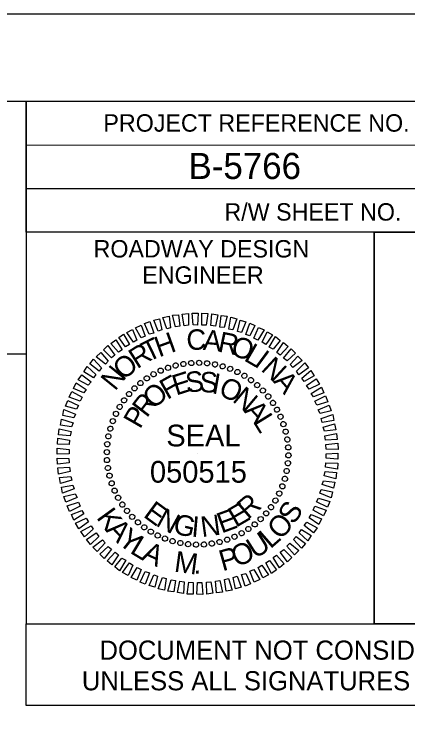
# Model space of a CAD drawing. Extents: x 573078 to 573156.2, y -55225.7 to -55195.8.
# Drawn here: x 573107.444 to 573109.707, y -55203.398 to -55199.298 of the extents above; entities that cross this region are included whole.
import ezdxf

# ---------------------------------------------------------------- set-up
doc = ezdxf.new("R2010")
doc.units = 0
for name, color, linetype in [('Prop Dimension', 7, 'Continuous'), ('Scratch_Level_1', 7, 'Continuous'), ('Sheet Data Field CELL', 7, 'Continuous'), ('Sheet Plan CELL', 7, 'Continuous'), ('Sheet Plot Border Inside CELL', 7, 'Continuous'), ('Sheet Sticker Exception Certification CELL', 7, 'Continuous')]:
    doc.layers.add(name, color=color, linetype=linetype)

msp = doc.modelspace()

# ---------------------------------------------------------------- linework, layer by layer
at = {"layer": 'Prop Dimension'}
for p, q in [((573108.3718, -55201.316), (573108.3718, -55201.316)), ((573108.4176, -55201.3077), (573108.4176, -55201.3077)), ((573108.4623, -55201.3015), (573108.4623, -55201.3015)), ((573108.5081, -55201.3005), (573108.5081, -55201.3005)), ((573108.5539, -55201.3035), (573108.5539, -55201.3035)), ((573108.5988, -55201.3109), (573108.5988, -55201.3109)), ((573108.6425, -55201.3202), (573108.6425, -55201.3202)), ((573108.2864, -55201.3452), (573108.2864, -55201.3452)), ((573108.328, -55201.3285), (573108.328, -55201.3285)), ((573108.6863, -55201.3348), (573108.6863, -55201.3348)), ((573108.7279, -55201.3535), (573108.7279, -55201.3535)), ((573108.2061, -55201.3901), (573108.2061, -55201.3901)), ((573108.2457, -55201.366), (573108.2457, -55201.366)), ((573108.7684, -55201.3744), (573108.7684, -55201.3744)), ((573108.8059, -55201.4005), (573108.8059, -55201.4005)), ((573108.1698, -55201.416), (573108.1698, -55201.416)), ((573108.8425, -55201.4285), (573108.8425, -55201.4285)), ((573108.104, -55201.4796), (573108.104, -55201.4796)), ((573108.1353, -55201.4473), (573108.1353, -55201.4473)), ((573108.8746, -55201.4597), (573108.8746, -55201.4597)), ((573108.076, -55201.516), (573108.076, -55201.516)), ((573108.9059, -55201.4942), (573108.9059, -55201.4942)), ((573108.0499, -55201.5535), (573108.0499, -55201.5535)), ((573108.932, -55201.5306), (573108.932, -55201.5306)), ((573108.0291, -55201.5942), (573108.0291, -55201.5942)), ((573108.9559, -55201.5701), (573108.9559, -55201.5701)), ((573108.0103, -55201.6359), (573108.0103, -55201.6359)), ((573108.9767, -55201.6109), (573108.9767, -55201.6109)), ((573107.9957, -55201.6796), (573107.9957, -55201.6796)), ((573108.9934, -55201.6525), (573108.9934, -55201.6525)), ((573107.9865, -55201.7233), (573107.9865, -55201.7233)), ((573109.0059, -55201.6963), (573109.0059, -55201.6963)), ((573107.9791, -55201.768), (573107.9791, -55201.768)), ((573109.0142, -55201.7421), (573109.0142, -55201.7421)), ((573109.0204, -55201.7867), (573109.0204, -55201.7867)), ((573107.9761, -55201.8138), (573107.9761, -55201.8138)), ((573108.4988, -55201.8233), (573108.4988, -55201.8233)), ((573109.0216, -55201.8326), (573109.0216, -55201.8326)), ((573107.977, -55201.8596), (573107.977, -55201.8596)), ((573109.0184, -55201.8784), (573109.0184, -55201.8784)), ((573107.9832, -55201.9045), (573107.9832, -55201.9045)), ((573109.0112, -55201.9233), (573109.0112, -55201.9233)), ((573107.9916, -55201.9504), (573107.9916, -55201.9504)), ((573109.0017, -55201.967), (573109.0017, -55201.967)), ((573108.0041, -55201.9941), (573108.0041, -55201.9941)), ((573108.9871, -55202.0108), (573108.9871, -55202.0108)), ((573108.0207, -55202.0357), (573108.0207, -55202.0357)), ((573108.9684, -55202.0524), (573108.9684, -55202.0524)), ((573108.0415, -55202.0762), (573108.0415, -55202.0762)), ((573108.9475, -55202.0929), (573108.9475, -55202.0929)), ((573108.0656, -55202.1158), (573108.0656, -55202.1158)), ((573108.9216, -55202.1304), (573108.9216, -55202.1304)), ((573108.0915, -55202.1524), (573108.0915, -55202.1524)), ((573108.8934, -55202.167), (573108.8934, -55202.167)), ((573108.1228, -55202.1866), (573108.1228, -55202.1866)), ((573108.1552, -55202.2179), (573108.1552, -55202.2179)), ((573108.8622, -55202.1991), (573108.8622, -55202.1991)), ((573108.1915, -55202.2461), (573108.1915, -55202.2461)), ((573108.7913, -55202.2565), (573108.7913, -55202.2565)), ((573108.8279, -55202.2304), (573108.8279, -55202.2304)), ((573108.229, -55202.272), (573108.229, -55202.272)), ((573108.2697, -55202.2929), (573108.2697, -55202.2929)), ((573108.7113, -55202.3012), (573108.7113, -55202.3012)), ((573108.7518, -55202.2804), (573108.7518, -55202.2804)), ((573108.3114, -55202.3116), (573108.3114, -55202.3116)), ((573108.3551, -55202.3262), (573108.3551, -55202.3262)), ((573108.3989, -55202.3357), (573108.3989, -55202.3357)), ((573108.4435, -55202.3428), (573108.4435, -55202.3428)), ((573108.5352, -55202.3449), (573108.5352, -55202.3449)), ((573108.5801, -55202.3387), (573108.5801, -55202.3387)), ((573108.6259, -55202.3303), (573108.6259, -55202.3303)), ((573108.6696, -55202.3178), (573108.6696, -55202.3178)), ((573108.4893, -55202.3461), (573108.4893, -55202.3461))]:
    msp.add_line(p, q, dxfattribs=at)
for points in [[(573108.3218, -55201.1057), (573108.2998, -55201.0402), (573108.3352, -55201.0328), (573108.3435, -55201.1006)], [(573108.3718, -55201.0943), (573108.3551, -55201.0277), (573108.3894, -55201.0245), (573108.3968, -55201.0911)], [(573108.4218, -55201.0881), (573108.4102, -55201.0214), (573108.4456, -55201.0173), (573108.4468, -55201.0849)], [(573108.4738, -55201.0828), (573108.4685, -55201.0152), (573108.503, -55201.0161), (573108.4988, -55201.0839)], [(573108.5238, -55201.0839), (573108.5238, -55201.0161), (573108.5581, -55201.0173), (573108.5488, -55201.0848)], [(573108.5759, -55201.0869), (573108.5801, -55201.0194), (573108.6143, -55201.0256), (573108.6009, -55201.0911)], [(573108.6259, -55201.0953), (573108.6351, -55201.0286), (573108.6696, -55201.0339), (573108.6509, -55201.0985)], [(573108.2207, -55201.136), (573108.1936, -55201.0756), (573108.2248, -55201.0631), (573108.2468, -55201.1297)], [(573108.2718, -55201.1193), (573108.2477, -55201.0568), (573108.2801, -55201.0474), (573108.2936, -55201.1119)], [(573108.6789, -55201.1068), (573108.6893, -55201.039), (573108.7247, -55201.0474), (573108.7009, -55201.1119)], [(573108.7289, -55201.1203), (573108.7446, -55201.0557), (573108.7768, -55201.0661), (573108.7508, -55201.1277)], [(573108.7758, -55201.139), (573108.7997, -55201.0735), (573108.8288, -55201.086), (573108.7997, -55201.1464)], [(573108.1302, -55201.1827), (573108.0915, -55201.1265), (573108.1239, -55201.1098), (573108.1499, -55201.1702)], [(573108.1748, -55201.1577), (573108.1415, -55201.0994), (573108.1739, -55201.0849), (573108.1978, -55201.1485)], [(573108.8226, -55201.1589), (573108.8487, -55201.0974), (573108.8809, -55201.1119), (573108.8455, -55201.1702)], [(573108.0844, -55201.2089), (573108.0457, -55201.1557), (573108.0728, -55201.136), (573108.1073, -55201.1964)], [(573108.8705, -55201.1827), (573108.8987, -55201.1235), (573108.93, -55201.1411), (573108.8904, -55201.1952)], [(573108.9112, -55201.211), (573108.9475, -55201.1506), (573108.9746, -55201.1723), (573108.9341, -55201.2235)], [(573108.0448, -55201.2401), (573107.9999, -55201.1901), (573108.0281, -55201.1682), (573108.0645, -55201.2265)], [(573108.9538, -55201.2422), (573108.9924, -55201.1848), (573109.0195, -55201.2077), (573108.9737, -55201.2568)], [(573108.0031, -55201.2723), (573107.9573, -55201.2265), (573107.9823, -55201.2015), (573108.0228, -55201.2577)], [(573108.9934, -55201.2744), (573109.0362, -55201.2202), (573109.0612, -55201.2452), (573109.0133, -55201.2901)], [(573107.9687, -55201.3089), (573107.9157, -55201.2661), (573107.9416, -55201.2422), (573107.9853, -55201.2922)], [(573109.0309, -55201.3109), (573109.0757, -55201.2619), (573109.1007, -55201.2869), (573109.0466, -55201.3276)], [(573107.9323, -55201.3484), (573107.8782, -55201.3077), (573107.9011, -55201.2806), (573107.9469, -55201.3297)], [(573109.0674, -55201.3484), (573109.1153, -55201.3015), (573109.1371, -55201.3297), (573109.082, -55201.3693)], [(573107.9011, -55201.388), (573107.8448, -55201.3526), (573107.8645, -55201.3223), (573107.9145, -55201.3681)], [(573109.0987, -55201.3889), (573109.1496, -55201.3452), (573109.1695, -55201.3755), (573109.1112, -55201.4088)], [(573107.8698, -55201.4297), (573107.8115, -55201.3984), (573107.8323, -55201.3693), (573107.8865, -55201.4109)], [(573109.1257, -55201.4317), (573109.1808, -55201.3922), (573109.2007, -55201.4234), (573109.1403, -55201.4526)], [(573107.8448, -55201.4743), (573107.7854, -55201.4484), (573107.8011, -55201.416), (573107.8573, -55201.4547)], [(573109.1528, -55201.4776), (573109.2111, -55201.441), (573109.2245, -55201.4734), (573109.1653, -55201.4972)], [(573107.824, -55201.5222), (573107.7594, -55201.4984), (573107.775, -55201.466), (573107.8344, -55201.4993)], [(573107.8032, -55201.5681), (573107.7386, -55201.5493), (573107.752, -55201.5171), (573107.8145, -55201.5463)], [(573109.1736, -55201.5222), (573109.235, -55201.491), (573109.2486, -55201.5243), (573109.1841, -55201.5451)], [(573109.1924, -55201.5713), (573109.2558, -55201.5442), (573109.2674, -55201.5764), (573109.2028, -55201.593)], [(573107.7875, -55201.618), (573107.7229, -55201.6046), (573107.7303, -55201.5701), (573107.7958, -55201.5963)], [(573109.209, -55201.6213), (573109.2757, -55201.5972), (573109.2819, -55201.6317), (573109.2162, -55201.643)], [(573107.774, -55201.668), (573107.7095, -55201.6597), (573107.7166, -55201.6243), (573107.7824, -55201.6463)], [(573107.7657, -55201.7213), (573107.699, -55201.715), (573107.7032, -55201.6796), (573107.7708, -55201.6963)], [(573109.2215, -55201.6713), (573109.287, -55201.6514), (573109.2933, -55201.6868), (573109.2278, -55201.693)], [(573109.2308, -55201.7212), (573109.2986, -55201.7067), (573109.3016, -55201.7421), (573109.235, -55201.7462)], [(573107.7604, -55201.7712), (573107.6928, -55201.7692), (573107.6949, -55201.7347), (573107.7625, -55201.7462)], [(573109.237, -55201.7712), (573109.3049, -55201.7629), (573109.3069, -55201.7983), (573109.2391, -55201.7962)], [(573107.7594, -55201.8233), (573107.6916, -55201.8263), (573107.6916, -55201.7909), (573107.7594, -55201.7983)], [(573107.7604, -55201.8754), (573107.6928, -55201.8837), (573107.6907, -55201.8483), (573107.7583, -55201.8504)], [(573109.2382, -55201.8233), (573109.3058, -55201.8201), (573109.3058, -55201.8555), (573109.2382, -55201.8483)], [(573109.237, -55201.8754), (573109.3049, -55201.8775), (573109.3028, -55201.9117), (573109.235, -55201.9004)], [(573107.7666, -55201.9254), (573107.6991, -55201.9399), (573107.6958, -55201.9045), (573107.7625, -55201.9004)], [(573109.232, -55201.9254), (573109.2986, -55201.9316), (573109.2944, -55201.967), (573109.2266, -55201.9504)], [(573107.7761, -55201.9753), (573107.7104, -55201.995), (573107.7041, -55201.9596), (573107.7699, -55201.9534)], [(573107.7886, -55202.0253), (573107.722, -55202.0492), (573107.7157, -55202.0149), (573107.7812, -55202.0033)], [(573109.2236, -55201.9784), (573109.2882, -55201.9867), (573109.2808, -55202.0221), (573109.2153, -55202.0003)], [(573107.8053, -55202.0753), (573107.7416, -55202.1024), (573107.7303, -55202.07), (573107.7949, -55202.0533)], [(573109.21, -55202.0283), (573109.2745, -55202.042), (573109.2674, -55202.0762), (573109.2016, -55202.0503)], [(573109.1945, -55202.0783), (573109.259, -55202.0971), (573109.2454, -55202.1295), (573109.1829, -55202.1003)], [(573107.824, -55202.1241), (573107.7625, -55202.1554), (573107.749, -55202.1221), (573107.8136, -55202.1012)], [(573109.1736, -55202.1241), (573109.2382, -55202.1482), (573109.2225, -55202.1804), (573109.1632, -55202.1471)], [(573107.8448, -55202.169), (573107.7865, -55202.2054), (573107.7729, -55202.1732), (573107.8323, -55202.1491)], [(573109.1528, -55202.172), (573109.2121, -55202.1982), (573109.1966, -55202.2304), (573109.1403, -55202.192)], [(573107.8719, -55202.2149), (573107.8166, -55202.2544), (573107.7969, -55202.2232), (573107.8573, -55202.194)], [(573109.1278, -55202.2169), (573109.1861, -55202.2482), (573109.1653, -55202.2773), (573109.1112, -55202.2357)], [(573107.899, -55202.2574), (573107.8479, -55202.3012), (573107.8282, -55202.2711), (573107.8865, -55202.2378)], [(573109.0966, -55202.2586), (573109.1528, -55202.294), (573109.1329, -55202.3241), (573109.0829, -55202.2783)], [(573107.9302, -55202.2982), (573107.8823, -55202.3449), (573107.8603, -55202.3169), (573107.9157, -55202.2773)], [(573109.0653, -55202.2982), (573109.1195, -55202.3387), (573109.0966, -55202.3657), (573109.0508, -55202.3169)], [(573107.9666, -55202.3357), (573107.9219, -55202.3845), (573107.8969, -55202.3595), (573107.9511, -55202.319)], [(573109.0288, -55202.3377), (573109.082, -55202.3803), (573109.0558, -55202.4044), (573109.0121, -55202.3544)], [(573108.0041, -55202.372), (573107.9615, -55202.4261), (573107.9365, -55202.4012), (573107.9844, -55202.3565)], [(573108.9945, -55202.3741), (573109.0403, -55202.4199), (573109.0154, -55202.4449), (573108.9746, -55202.3887)], [(573108.0436, -55202.4044), (573108.0052, -55202.4616), (573107.9781, -55202.4386), (573108.024, -55202.3898)], [(573108.0864, -55202.4356), (573108.0499, -55202.496), (573108.0228, -55202.474), (573108.0635, -55202.4231)], [(573108.9529, -55202.4065), (573108.9975, -55202.4565), (573108.9695, -55202.4782), (573108.933, -55202.4199)], [(573108.1269, -55202.4636), (573108.0989, -55202.5231), (573108.0677, -55202.5053), (573108.1073, -55202.4511)], [(573108.8675, -55202.4636), (573108.9059, -55202.5199), (573108.8737, -55202.5365), (573108.8476, -55202.4761)], [(573108.9133, -55202.4377), (573108.9517, -55202.4907), (573108.9246, -55202.5106), (573108.8904, -55202.4502)], [(573108.1748, -55202.4877), (573108.1489, -55202.549), (573108.1165, -55202.5345), (573108.1519, -55202.4761)], [(573108.2218, -55202.5074), (573108.1978, -55202.5731), (573108.1686, -55202.5606), (573108.1978, -55202.5002)], [(573108.8226, -55202.4886), (573108.8559, -55202.5469), (573108.8237, -55202.5615), (573108.7997, -55202.4981)], [(573108.2686, -55202.5261), (573108.2531, -55202.5907), (573108.2207, -55202.5803), (573108.2468, -55202.5189)], [(573108.3186, -55202.5398), (573108.3081, -55202.6073), (573108.2727, -55202.599), (573108.2968, -55202.5345)], [(573108.3718, -55202.5511), (573108.3623, -55202.6178), (573108.328, -55202.6127), (573108.3468, -55202.5481)], [(573108.6759, -55202.5407), (573108.6976, -55202.6064), (573108.6622, -55202.6136), (573108.6539, -55202.546)], [(573108.7258, -55202.5273), (573108.7497, -55202.5898), (573108.7175, -55202.599), (573108.7039, -55202.5344)], [(573108.7768, -55202.5106), (573108.8038, -55202.571), (573108.7726, -55202.5835), (573108.7508, -55202.5169)], [(573108.4218, -55202.5594), (573108.4176, -55202.6272), (573108.3831, -55202.621), (573108.3968, -55202.5553)], [(573108.4738, -55202.5627), (573108.4738, -55202.6303), (573108.4394, -55202.6293), (573108.4488, -55202.5615)], [(573108.5238, -55202.5636), (573108.5289, -55202.6314), (573108.4947, -55202.6303), (573108.4988, -55202.5627)], [(573108.5759, -55202.5585), (573108.5872, -55202.6252), (573108.5518, -55202.6293), (573108.5509, -55202.5615)], [(573108.6259, -55202.5523), (573108.6425, -55202.6189), (573108.6081, -55202.6219), (573108.6009, -55202.5553)]]:
    msp.add_lwpolyline(points, close=True, dxfattribs=at)
for centre, major_axis in [((573108.3288, -55201.3293), (-0.0049, 0.0142)), ((573108.3725, -55201.3164), (-0.0036, 0.0146)), ((573108.4171, -55201.3073), (-0.0023, 0.0148)), ((573108.4624, -55201.3022), (-0.001, 0.015)), ((573108.508, -55201.301), (0.0003, 0.015)), ((573108.5534, -55201.3037), (0.0016, 0.0149)), ((573108.5985, -55201.3105), (0.0029, 0.0147)), ((573108.6428, -55201.3211), (0.0041, 0.0144)), ((573108.686, -55201.3356), (0.0054, 0.014)), ((573108.2456, -55201.3664), (-0.0073, 0.0131)), ((573108.2864, -55201.346), (-0.0061, 0.0137)), ((573108.7278, -55201.3538), (0.0066, 0.0135)), ((573108.7679, -55201.3755), (0.0077, 0.0129)), ((573108.1701, -55201.4173), (-0.0094, 0.0117)), ((573108.2067, -55201.3902), (-0.0084, 0.0124)), ((573108.8059, -55201.4006), (0.0088, 0.0121)), ((573108.136, -55201.4475), (-0.0104, 0.0108)), ((573108.8415, -55201.429), (0.0098, 0.0113)), ((573108.1046, -55201.4805), (-0.0113, 0.0098)), ((573108.8746, -55201.4604), (0.0108, 0.0104)), ((573108.9048, -55201.4945), (0.0117, 0.0094)), ((573108.0762, -55201.5162), (-0.0121, 0.0088)), ((573108.9319, -55201.5311), (0.0124, 0.0084)), ((573108.0511, -55201.5542), (-0.0129, 0.0077)), ((573108.9557, -55201.57), (0.0131, 0.0073)), ((573108.0294, -55201.5943), (-0.0135, 0.0066)), ((573108.976, -55201.6108), (0.0137, 0.0061)), ((573108.0112, -55201.636), (-0.014, 0.0054)), ((573108.9927, -55201.6532), (0.0142, 0.0049)), ((573107.9967, -55201.6793), (-0.0144, 0.0041)), ((573109.0057, -55201.6969), (0.0146, 0.0036)), ((573107.9861, -55201.7236), (-0.0147, 0.0029)), ((573109.0148, -55201.7415), (0.0148, 0.0023)), ((573107.9793, -55201.7686), (-0.0149, 0.0016)), ((573107.9766, -55201.8141), (-0.015, 0.0003)), ((573109.0199, -55201.7868), (0.015, 0.001)), ((573107.9778, -55201.8597), (-0.015, -0.001)), ((573109.0211, -55201.8324), (0.015, -0.0003)), ((573107.9829, -55201.905), (-0.0148, -0.0023)), ((573109.0183, -55201.8778), (0.0149, -0.0016)), ((573107.992, -55201.9496), (-0.0146, -0.0036)), ((573109.0116, -55201.9229), (0.0147, -0.0029)), ((573109.001, -55201.9672), (0.0144, -0.0041)), ((573108.0049, -55201.9933), (-0.0142, -0.0049)), ((573108.9865, -55202.0104), (0.014, -0.0054)), ((573108.0216, -55202.0357), (-0.0137, -0.0061)), ((573108.9683, -55202.0522), (0.0135, -0.0066)), ((573108.042, -55202.0765), (-0.0131, -0.0073)), ((573108.0658, -55202.1153), (-0.0124, -0.0084)), ((573108.9466, -55202.0923), (0.0129, -0.0077)), ((573108.0929, -55202.152), (-0.0117, -0.0094)), ((573108.9214, -55202.1303), (0.0121, -0.0088)), ((573108.1231, -55202.1861), (-0.0108, -0.0104)), ((573108.8931, -55202.1659), (0.0113, -0.0098)), ((573108.1561, -55202.2175), (-0.0098, -0.0113)), ((573108.8276, -55202.2292), (0.0094, -0.0117)), ((573108.8617, -55202.199), (0.0104, -0.0108)), ((573108.1918, -55202.2458), (-0.0088, -0.0121)), ((573108.2298, -55202.271), (-0.0077, -0.0129)), ((573108.7521, -55202.2801), (0.0073, -0.0131)), ((573108.7909, -55202.2563), (0.0084, -0.0124)), ((573108.2699, -55202.2927), (-0.0066, -0.0135)), ((573108.3116, -55202.3109), (-0.0054, -0.014)), ((573108.6689, -55202.3171), (0.0049, -0.0142)), ((573108.7113, -55202.3004), (0.0061, -0.0137)), ((573108.3549, -55202.3254), (-0.0041, -0.0144)), ((573108.3992, -55202.336), (-0.0029, -0.0147)), ((573108.4442, -55202.3427), (-0.0016, -0.0149)), ((573108.4897, -55202.3455), (-0.0003, -0.015)), ((573108.5353, -55202.3443), (0.001, -0.015)), ((573108.5806, -55202.3392), (0.0023, -0.0148)), ((573108.6252, -55202.3301), (0.0036, -0.0146))]:
    msp.add_ellipse(centre, major_axis=major_axis, ratio=0.999708, dxfattribs=at)
at = {"layer": 'Scratch_Level_1'}
msp.add_line((573108.4988, -55201.8233), (573108.4988, -55201.8233), dxfattribs=at)
at = {"layer": 'Sheet Plan CELL'}
for p, q in [((573107.5132, -55200.0494), (573111.5142, -55200.0497)), ((573107.5132, -55200.3002), (573111.5142, -55200.2997)), ((573109.5142, -55200.5499), (573109.5144, -55202.7992)), ((573107.5132, -55203.2699), (573107.5132, -55202.7999))]:
    msp.add_line(p, q, dxfattribs=at)
for points in [[(573081.5142, -55199.7984), (573111.5142, -55199.7984), (573111.5142, -55220.7984), (573081.5142, -55220.7984)], [(573107.5132, -55201.252), (573104.5124, -55201.252), (573104.5124, -55199.7984), (573107.5132, -55199.7984)], [(573107.5132, -55199.7984), (573111.5142, -55199.7984), (573111.5142, -55200.5499), (573107.5132, -55200.5499)], [(573109.5142, -55200.5499), (573107.5132, -55200.5499), (573107.5132, -55202.7999), (573109.5142, -55202.7999)], [(573109.5142, -55200.5499), (573111.5142, -55200.5499), (573111.5142, -55202.7999), (573109.5142, -55202.7999)]]:
    msp.add_lwpolyline(points, close=True, dxfattribs=at)
at = {"layer": 'Sheet Plot Border Inside CELL'}
msp.add_lwpolyline([(573112.0142, -55199.2984), (573078.0142, -55199.2984), (573078.0142, -55221.2984), (573112.0142, -55221.2984)], close=True, dxfattribs=at)
at = {"layer": 'Sheet Sticker Exception Certification CELL'}
for p, q in [((573107.5132, -55202.7999), (573111.5142, -55202.7999)), ((573111.5139, -55203.2699), (573107.5132, -55203.2699))]:
    msp.add_line(p, q, dxfattribs=at)

# ---------------------------------------------------------------- texts
at = {"layer": 'Prop Dimension'}
for s, height, rotation, p in [('C', 0.1177, 1.0718, (573108.4354, -55201.2274)), ('A', 0.1177, 354.8222, (573108.5271, -55201.2262)), ('T', 0.1177, 26.0703, (573108.2137, -55201.2991)), ('H', 0.1177, 19.8207, (573108.2771, -55201.27)), ('R', 0.1177, 348.5725, (573108.6104, -55201.2357)), ('O', 0.1177, 342.3229, (573108.6833, -55201.2545)), ('R', 0.1177, 32.3199, (573108.1512, -55201.3387)), ('L', 0.1177, 329.8237, (573108.7594, -55201.2846)), ('I', 0.1177, 323.5741, (573108.8177, -55201.3149)), ('O', 0.1177, 38.5695, (573108.0709, -55201.4044)), ('N', 0.1177, 317.3244, (573108.8582, -55201.342)), ('N', 0.1177, 51.0688, (573108.0242, -55201.4669)), ('E', 0.1177, 17.6709, (573108.375, -55201.4898)), ('S', 0.1177, 6.1833, (573108.4354, -55201.4732)), ('S', 0.1177, 358.4778, (573108.5095, -55201.4699)), ('F', 0.1177, 29.3, (573108.3241, -55201.5148)), ('I', 0.1177, 350.0931, (573108.5761, -55201.4753)), ('O', 0.1177, 335.3611, (573108.6125, -55201.4824)), ('A', 0.1177, 311.0748, (573108.9302, -55201.4095)), ('O', 0.1177, 43.5875, (573108.2501, -55201.5711)), ('N', 0.1177, 319.95, (573108.6937, -55201.519)), ('R', 0.1177, 52.4166, (573108.2063, -55201.621)), ('P', 0.1177, 60.1222, (573108.1679, -55201.6856)), ('A', 0.1177, 312.2445, (573108.7624, -55201.5803)), ('L', 0.1177, 301.6752, (573108.8145, -55201.6386)), ('SEAL', 0.12497, 360, (573108.3188, -55201.7814)), ('050515', 0.12497, 360, (573108.2247, -55201.9897)), ('E', 0.1177, 323.6798, (573108.1813, -55202.1822)), ('R', 0.1177, 40.7353, (573108.7886, -55202.2042)), ('S', 0.12, 57.1863, (573109.0532, -55202.2356)), ('K', 0.12, 305.9043, (573107.9134, -55202.1903)), ('N', 0.1177, 331.3854, (573108.2533, -55202.2334)), ('E', 0.1177, 20.0411, (573108.6365, -55202.2822)), ('E', 0.1177, 30.1214, (573108.7187, -55202.25)), ('G', 0.1177, 346.7965, (573108.3521, -55202.2792)), ('N', 0.1177, 7.7341, (573108.5241, -55202.303)), ('O', 0.12, 47.4888, (573108.9759, -55202.3231)), ('A', 0.12, 313.5599, (573107.9675, -55202.265)), ('I', 0.1177, 355.0405, (573108.4604, -55202.2989)), ('Y', 0.12, 321.5623, (573108.0342, -55202.3347)), ('L', 0.12, 328.9868, (573108.1042, -55202.3904)), ('U', 0.12, 32.399, (573108.8293, -55202.43)), ('L', 0.12, 41.0852, (573108.9172, -55202.3732)), ('A', 0.12, 335.3904, (573108.1699, -55202.4309)), ('O', 0.12, 22.7015, (573108.7224, -55202.477)), ('M', 0.12, 352.2427, (573108.3601, -55202.5002)), ('P', 0.12, 15.7778, (573108.642, -55202.4992)), ('.', 0.12, 1.9209, (573108.4759, -55202.5138))]:
    msp.add_text(s, height=height, rotation=rotation, dxfattribs=at).set_placement(p)
at = {"layer": 'Sheet Data Field CELL'}
msp.add_text('B-5766', height=0.15, rotation=0, dxfattribs=at).set_placement((573108.4467, -55200.2449))
at = {"layer": 'Sheet Plan CELL'}
for s, height, p in [('PROJECT REFERENCE NO.', 0.100002, (573107.9572, -55199.9729)), ('R/W SHEET NO.', 0.100002, (573108.6532, -55200.4839)), ('ROADWAY DESIGN', 0.100002, (573107.9007, -55200.6959)), ('ENGINEER', 0.1, (573108.1804, -55200.8467))]:
    msp.add_text(s, height=height, rotation=0, dxfattribs=at).set_placement(p)
at = {"layer": 'Sheet Sticker Exception Certification CELL'}
for s, p in [('DOCUMENT NOT CONSIDERED FINAL', (573107.9346, -55203.0068)), ('UNLESS ALL SIGNATURES COMPLETED', (573107.8332, -55203.1828))]:
    msp.add_text(s, height=0.11, dxfattribs=at).set_placement(p)

doc.saveas('drawing.dxf')
